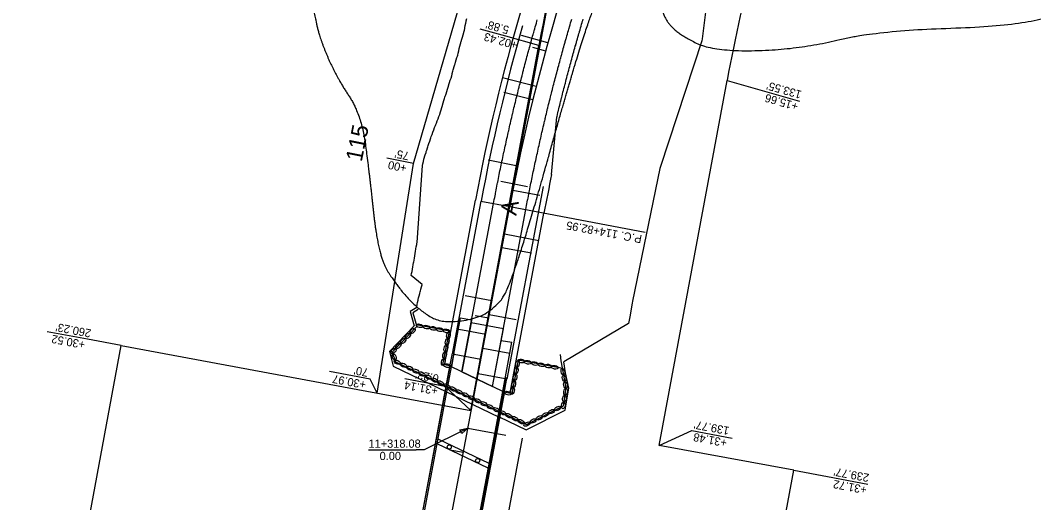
# Model space of a CAD drawing. Extents: x 674098 to 689971, y 764717 to 781049.
# Drawn here: x 688378 to 689119, y 766344 to 766697 of the extents above; entities that cross this region are included whole.
import ezdxf

# ---------------------------------------------------------------- set-up
doc = ezdxf.new("R2010")
doc.units = 0
for name, color, linetype in [('BRIDGE', 7, 'Continuous'), ('FLOODPLAIN', 7, 'Continuous'), ('Level 1', 7, 'Continuous'), ('R_Approach Slab', 7, 'Continuous'), ('R_GUARDRAIL S1', 7, 'Continuous'), ('R_GUARDRAIL S2', 7, 'Continuous'), ('R_Horz Alg', 7, 'Continuous'), ('R_Horz Alg Station', 7, 'Continuous'), ('R_Horz Alg Station Annot', 7, 'Continuous'), ('R_No Plot', 7, 'Continuous'), ('R_Proposed Const Limits', 7, 'Continuous'), ('R_Proposed Const Limits Stage 2', 7, 'Continuous'), ('R_Proposed Riprap', 7, 'Continuous'), ('R_Proposed Riprap MOT Stage 2', 7, 'Continuous'), ('R_Proposed Road', 7, 'Continuous'), ('R_Proposed Shoulder S1', 7, 'Continuous'), ('R_ROW', 7, 'Continuous'), ('R_ROW Annot', 7, 'Continuous'), ('S_EXIST_ROW', 7, 'Continuous'), ('S_EXIST_ROW Annot', 7, 'Continuous')]:
    doc.layers.add(name, color=color, linetype=linetype)

msp = doc.modelspace()

# ---------------------------------------------------------------- linework, layer by layer
at = {"layer": 'BRIDGE'}
for p, q in [((688645.49, 766197.09), (688691.88, 766443.79)), ((688645.65, 766197.06), (688692.05, 766443.76)), ((688646.72, 766196.86), (688693.11, 766443.56)), ((688693.11, 766443.56), (688691.88, 766443.79)), ((688730.44, 766425.64), (688693.11, 766443.56)), ((688684.05, 766178.93), (688730.44, 766425.64)), ((688685.11, 766178.73), (688731.51, 766425.44)), ((688731.67, 766425.41), (688685.28, 766178.7)), ((688730.44, 766425.64), (688731.67, 766425.41))]:
    msp.add_line(p, q, dxfattribs=at)
for points in [[(688691.88, 766443.79), (688693.73, 766453.62), (688694.71, 766453.44), (688694.25, 766450.98), (688693.11, 766443.56)], [(688731.67, 766425.41), (688733.52, 766435.23), (688732.54, 766435.42), (688732.07, 766432.96), (688730.44, 766425.64)]]:
    msp.add_lwpolyline(points, dxfattribs=at)
at = {"layer": 'FLOODPLAIN'}
for points in [[(688557.23, 766766.05), (688591.58, 766711.04), (688595.35, 766687.04), (688608.48, 766656.15), (688627.02, 766628.3), (688632.82, 766586.19), (688639.4, 766524.53), (688653.57, 766501.98), (688669.3, 766485), (688687.59, 766474.45), (688723.13, 766481.9), (688739.6, 766509.51), (688789, 766687.63), (688806.98, 766729.19), (688822.47, 766746.61), (688835.88, 766751.3), (688842.63, 766741.88), (688846.4, 766712.12), (688847.97, 766698.77), (688859.62, 766686.41), (688884.96, 766674.2), (688946.59, 766675.74), (689003.92, 766689.73), (689113.2, 766693.11), (689155.64, 766709.56), (689222.69, 766748.31), (689278.94, 766804.47), (689325.37, 766856.38), (689397.34, 766962.93), (689435.45, 766991.81), (689488.41, 767032.29), (689550.62, 767060.41), (689676.67, 767118.63), (689783.6, 767157.05), (689856.65, 767174.65), (689971.45, 767193.2)], [(687636.99, 766648.35), (687660.7, 766676.39), (687679.12, 766678.93), (687695.79, 766668.17), (687704.23, 766666.19), (687721.96, 766671.63), (687744.74, 766707.43), (687761.28, 766716.58), (687819.2, 766729.75), (687857.32, 766757.84), (687886.19, 766778.49), (687909.82, 766800.04), (687916.33, 766827.84), (687921.35, 766849.28), (687933.23, 766850.3), (687942.45, 766841.87), (687953.68, 766811.48), (687955.55, 766791.78), (687937.94, 766767.25), (687928.38, 766752.25), (687934.01, 766743.77), (687949.02, 766743.84), (687978.06, 766759.86), (688017.53, 766789.79), (688029.63, 766786.96), (688058.51, 766774.59), (688076.54, 766770.37), (688098.38, 766788.35), (688128.58, 766823.59), (688146.89, 766829.88), (688224.87, 766848.43), (688351.93, 766870.25), (688387.57, 766861.9), (688478.61, 766846.38), (688494.31, 766842.7), (688540.43, 766797.53), (688557.23, 766766.05)]]:
    msp.add_open_spline(points, degree=2, dxfattribs=at)
at = {"layer": 'Level 1'}
for p, q in [((688719.86, 766369.36), (688682.53, 766387.29)), ((688720.51, 766372.8), (688683.18, 766390.73))]:
    msp.add_line(p, q, dxfattribs=at)
for centre in [(688691.35, 766384.93), (688712.13, 766374.95)]:
    msp.add_circle(centre, 1.5, dxfattribs=at)
at = {"layer": 'R_Approach Slab'}
for p, q in [((688693.11, 766443.56), (688699.65, 766479.47)), ((688699.65, 766479.47), (688707.73, 766478)), ((688707.73, 766478), (688707.31, 766475.77)), ((688729.32, 766462.94), (688736.98, 766461.55)), ((688730.44, 766425.64), (688736.98, 766461.55))]:
    msp.add_line(p, q, dxfattribs=at)
msp.add_lwpolyline([(688700.58, 766439.98), (688722.98, 766429.22), (688730.92, 766471.47), (688707.31, 766475.77)], close=True, dxfattribs=at)
at = {"layer": 'R_GUARDRAIL S1'}
msp.add_line((688693.62, 766453.03), (688714.63, 766564.76), dxfattribs=at)
msp.add_lwpolyline([(688719.48, 766367.32), (688719.46, 766367.25)], dxfattribs=at)
msp.add_arc((690143.23, 766296.11), 1453.64, 164.14725, 169.35, dxfattribs=at)
at = {"layer": 'R_GUARDRAIL S2'}
msp.add_line((688760.05, 766575.61), (688733.41, 766434.64), dxfattribs=at)
at = {"layer": 'R_Horz Alg'}
for p, q in [((688735.51, 766560.83), (688775.27, 766772.26)), ((688649.13, 766101.47), (688735.51, 766560.83)), ((688649.13, 766101.47), (688735.51, 766560.83))]:
    msp.add_line(p, q, dxfattribs=at)
msp.add_arc((690143.23, 766296.11), 1432.39, 152.26653, 169.35, dxfattribs=at)
msp.add_arc((690143.23, 766296.11), 1432.39, 152.26653, 169.35, dxfattribs=at)
at = {"layer": 'R_Horz Alg Station'}
for points in [[(688752.17, 766677.49), (688761.82, 766674.85)], [(688728.96, 766579.53), (688748.57, 766575.6)], [(688735.51, 766560.83), (688834.5, 766542.22)], [(688710.36, 766481.15), (688720.18, 766479.31)], [(688691.88, 766382.88), (688701.7, 766381.03)]]:
    msp.add_lwpolyline(points, dxfattribs=at)
at = {"layer": 'R_No Plot'}
for p, q in [((688763.42, 766680.65), (688744.16, 766686.02)), ((688754.93, 766648.76), (688730.22, 766655.04)), ((688752.5, 766639.06), (688731.14, 766644.33)), ((688741.38, 766590.32), (688719.85, 766594.84)), ((688737.82, 766572.96), (688757.48, 766569.15)), ((688714.41, 766564.8), (688735.51, 766560.83)), ((688756.76, 766535.82), (688731.7, 766540.53)), ((688751.47, 766526.64), (688729.85, 766530.71)), ((688702.93, 766495.8), (688722.59, 766492.1)), ((688740.26, 766477.87), (688720.61, 766481.57)), ((688698.31, 766471.23), (688717.97, 766467.53)), ((688694.85, 766452.8), (688714.5, 766449.11)), ((688735.64, 766453.3), (688715.99, 766457)), ((688732.18, 766434.88), (688712.52, 766438.57)), ((688705.04, 766398.8), (688732.61, 766393.61)), ((688744.63, 766391.33), (688710.59, 766209.69)), ((688632.33, 766382.88), (688667.13, 766382.88))]:
    msp.add_line(p, q, dxfattribs=at)
msp.add_lwpolyline([(688705.04, 766398.8), (688673.13, 766382.88), (688667.13, 766382.88)], dxfattribs=at)
msp.add_lwpolyline([(688705.04, 766398.8), (688700.48, 766394.9), (688699.19, 766397.5)], close=True, dxfattribs=at)
at = {"layer": 'R_Proposed Const Limits'}
for points in [[(688667.68, 766487.44), (688667.95, 766489.07), (688667.96, 766489.13), (688668.23, 766490.71), (688668.51, 766492.34), (688668.63, 766492.77), (688668.93, 766493.95), (688669.35, 766495.55), (688669.77, 766497.16), (688670.19, 766498.77), (688670.22, 766498.88), (688670.61, 766500.38), (688671.03, 766501.99), (688671.45, 766503.59), (688671.48, 766503.73), (688663.59, 766510.3), (688663.84, 766511.77), (688664.14, 766513.4), (688664.43, 766515.03), (688664.72, 766516.66), (688664.73, 766516.69), (688665.01, 766518.3), (688665.3, 766519.93), (688665.34, 766520.15), (688665.59, 766521.56), (688665.87, 766523.19), (688666.15, 766524.83), (688666.42, 766526.46), (688666.7, 766528.1), (688666.99, 766529.73), (688667.03, 766530), (688667.27, 766531.36), (688667.54, 766533), (688667.73, 766534.12), (688667.82, 766534.63), (688671.83, 766590.98), (688672.06, 766592.05), (688672.41, 766593.75), (688672.78, 766595.45), (688673.25, 766596.92), (688673.31, 766597.12), (688673.83, 766598.78), (688674.36, 766600.44), (688674.58, 766601.11), (688674.9, 766602.1), (688675.45, 766603.76), (688675.71, 766604.57), (688675.99, 766605.42), (688676.54, 766607.08), (688677.09, 766608.74), (688677.64, 766610.39), (688677.88, 766611.11), (688678.19, 766612.05), (688678.24, 766612.19), (688678.8, 766613.69), (688679.42, 766615.33), (688680.05, 766616.97), (688680.68, 766618.6), (688681.11, 766619.73), (688681.3, 766620.24), (688681.6, 766621), (688681.93, 766621.87), (688682.56, 766623.51), (688683.19, 766625.14), (688683.82, 766626.77), (688684.01, 766627.25), (688684.36, 766628.1), (688684.45, 766628.41), (688684.95, 766630.07), (688685.2, 766630.9), (688685.45, 766631.73), (688685.94, 766633.39), (688686.39, 766634.87), (688686.44, 766635.05), (688686.95, 766636.71), (688687.45, 766638.37), (688687.96, 766640.03), (688688.22, 766640.92), (688688.46, 766641.69), (688688.73, 766642.5), (688689, 766643.34), (688689.53, 766644.99), (688690.05, 766646.65), (688690.56, 766648.3), (688691.08, 766649.96), (688691.13, 766650.11), (688691.37, 766650.89), (688691.59, 766651.61), (688692.11, 766653.26), (688692.63, 766654.92), (688693.16, 766656.57), (688693.45, 766657.74), (688693.56, 766658.25), (688693.95, 766659.93), (688694.19, 766660.94), (688694.39, 766661.61), (688694.9, 766663.26), (688695.42, 766664.91), (688695.57, 766665.4), (688695.94, 766666.56), (688696.46, 766668.22), (688696.98, 766669.87), (688697.31, 766670.91), (688697.5, 766671.52), (688697.84, 766673.03), (688697.88, 766673.2), (688698.26, 766674.89), (688698.64, 766676.58), (688699.05, 766678.26), (688699.53, 766679.92), (688699.77, 766680.75), (688699.86, 766681.03), (688700.02, 766681.58), (688700.5, 766683.24), (688700.99, 766684.9), (688701.47, 766686.56), (688701.96, 766688.21), (688702.01, 766688.38), (688702.38, 766689.89), (688702.62, 766691.08), (688702.72, 766691.59), (688703.06, 766693.29), (688703.41, 766694.99), (688703.65, 766696.18), (688703.76, 766696.69), (688704.11, 766698.38)], [(688667.7, 766486.99), (688662.77, 766483.95), (688665.7, 766473.66), (688647.65, 766454.81), (688650.4, 766444.04), (688727.81, 766406.86)]]:
    msp.add_lwpolyline(points, dxfattribs=at)
at = {"layer": 'R_Proposed Const Limits Stage 2'}
for points in [[(688881.93, 766728.74), (688876.21, 766683.7), (688875.85, 766682.21), (688845.71, 766590.1), (688845.35, 766588.6), (688825.36, 766491.52), (688825.08, 766490.11), (688823.32, 766480.26), (688822.44, 766475.34), (688775.03, 766447.35)], [(688727.77, 766406.88), (688747.5, 766397.41), (688775.99, 766411.91), (688778.64, 766427.93), (688776.43, 766439.21), (688775.03, 766447.35)]]:
    msp.add_lwpolyline(points, dxfattribs=at)
at = {"layer": 'R_Proposed Riprap'}
msp.add_lwpolyline([(688668.6, 766485.52), (688664.78, 766483.17), (688667.62, 766473.18), (688649.63, 766454.39), (688652.16, 766447.32), (688747.86, 766401.36), (688774.82, 766415.08), (688776.9, 766427.9), (688774.74, 766438.9), (688773.16, 766448.04), (688772.62, 766452.51)], dxfattribs=at)
for centre, major_axis in [((688669.66, 766473.59), (2.46, -0.47)), ((688674.6, 766472.65), (2.46, -0.47)), ((688679.53, 766471.72), (2.46, -0.47)), ((688661.08, 766466.13), (1.73, 1.81)), ((688664.55, 766469.76), (1.73, 1.81)), ((688684.46, 766470.78), (2.46, -0.47)), ((688689.39, 766469.84), (2.46, -0.47)), ((688690.78, 766466.77), (-0.48, -2.45)), ((688654.14, 766458.88), (1.73, 1.81)), ((688657.61, 766462.51), (1.73, 1.81)), ((688688.86, 766456.92), (-0.48, -2.45)), ((688689.82, 766461.84), (-0.48, -2.45)), ((688650.67, 766455.26), (1.73, 1.81)), ((688651.01, 766450.98), (-0.84, 2.36)), ((688687.89, 766451.99), (-0.48, -2.45)), ((688653.3, 766446.94), (-2.25, 1.08)), ((688657.82, 766444.76), (-2.25, 1.08)), ((688662.35, 766442.59), (-2.25, 1.08)), ((688686.93, 766447.06), (-0.48, -2.45)), ((688689.79, 766444.47), (2.46, -0.46)), ((688666.87, 766440.42), (-2.25, 1.08)), ((688671.4, 766438.25), (-2.25, 1.08)), ((688675.92, 766436.07), (-2.25, 1.08)), ((688680.45, 766433.9), (-2.25, 1.08)), ((688684.97, 766431.73), (-2.25, 1.08)), ((688689.5, 766429.55), (-2.25, 1.08)), ((688694.02, 766427.38), (-2.25, 1.08)), ((688698.55, 766425.21), (-2.25, 1.08)), ((688703.07, 766423.03), (-2.25, 1.08)), ((688707.6, 766420.86), (-2.25, 1.08)), ((688712.12, 766418.69), (-2.25, 1.08)), ((688716.65, 766416.52), (-2.25, 1.08)), ((688721.17, 766414.34), (-2.25, 1.08)), ((688725.7, 766412.17), (-2.25, 1.08))]:
    msp.add_ellipse(centre, major_axis=major_axis, ratio=0.517889, dxfattribs=at)
at = {"layer": 'R_Proposed Riprap MOT Stage 2'}
for points in [[(688691.63, 766444.28), (688686.72, 766445.2), (688691.49, 766469.6), (688667.23, 766474.21)], [(688773.04, 766442.55), (688741.62, 766448.4), (688737.06, 766423.86), (688731.83, 766424.97)]]:
    msp.add_lwpolyline(points, dxfattribs=at)
for centre, major_axis in [((688740.36, 766440.79), (0.46, 2.46)), ((688741.28, 766445.72), (0.46, 2.46)), ((688743.88, 766447.83), (2.46, -0.46)), ((688748.82, 766446.91), (2.46, -0.46)), ((688753.75, 766445.99), (2.46, -0.46)), ((688758.69, 766445.07), (2.46, -0.46)), ((688763.62, 766444.15), (2.46, -0.46)), ((688768.56, 766443.23), (2.46, -0.46)), ((688739.44, 766435.85), (0.46, 2.46)), ((688774.38, 766440.08), (0.43, -2.46)), ((688775.32, 766435.15), (0.48, -2.45)), ((688737.61, 766425.98), (0.46, 2.46)), ((688738.52, 766430.92), (0.46, 2.46)), ((688776.29, 766430.22), (0.48, -2.45)), ((688734.26, 766424.3), (2.45, -0.52)), ((688775.52, 766420.38), (-0.4, -2.47)), ((688776.33, 766425.33), (-0.4, -2.47)), ((688770.56, 766413.08), (-2.23, -1.13)), ((688774.72, 766415.42), (-0.4, -2.47)), ((688730.23, 766410), (-2.25, 1.08)), ((688734.75, 766407.82), (-2.25, 1.08)), ((688739.28, 766405.65), (-2.25, 1.08)), ((688757.14, 766406.25), (-2.23, -1.13)), ((688761.61, 766408.53), (-2.23, -1.13)), ((688766.09, 766410.81), (-2.23, -1.13)), ((688743.8, 766403.48), (-2.25, 1.08)), ((688748.19, 766401.7), (-2.23, -1.13)), ((688752.66, 766403.98), (-2.23, -1.13))]:
    msp.add_ellipse(centre, major_axis=major_axis, ratio=0.517889, dxfattribs=at)
at = {"layer": 'R_Proposed Road'}
for points in [[(688700.58, 766439.98), (688723.72, 766563.05), (688723.75, 766563.22), (688724.02, 766564.62), (688724.28, 766566.02), (688724.55, 766567.42), (688724.82, 766568.82), (688725.05, 766570.03), (688725.09, 766570.23), (688725.16, 766570.6), (688725.36, 766571.63), (688725.63, 766573.03), (688725.91, 766574.43), (688726.18, 766575.83), (688726.46, 766577.23), (688726.64, 766578.15), (688726.74, 766578.63), (688727, 766579.92), (688727.02, 766580.03), (688727.3, 766581.42), (688727.58, 766582.82), (688727.87, 766584.22), (688728.15, 766585.62), (688728.17, 766585.69), (688728.44, 766587.02), (688728.73, 766588.42), (688729.01, 766589.8), (688729.02, 766589.81), (688729.31, 766591.21), (688729.6, 766592.61), (688729.73, 766593.22), (688729.89, 766594), (688730.19, 766595.4), (688730.48, 766596.79), (688730.78, 766598.19), (688731.08, 766599.58), (688731.1, 766599.67), (688731.33, 766600.74), (688731.38, 766600.98), (688731.68, 766602.37), (688731.99, 766603.77), (688732.29, 766605.16), (688732.6, 766606.56), (688732.9, 766607.95), (688732.97, 766608.25), (688733.21, 766609.34), (688733.25, 766609.52), (688733.52, 766610.74), (688733.84, 766612.13), (688734.15, 766613.52), (688734.46, 766614.91), (688734.65, 766615.76), (688734.78, 766616.31), (688735.09, 766617.7), (688735.41, 766619.09), (688735.45, 766619.26), (688735.48, 766619.36), (688735.73, 766620.48), (688736.05, 766621.87), (688736.37, 766623.25), (688736.38, 766623.26), (688736.7, 766624.65), (688737.03, 766626.04), (688737.35, 766627.43), (688737.68, 766628.81), (688737.77, 766629.18), (688738.01, 766630.2), (688738.14, 766630.74), (688738.34, 766631.59), (688738.67, 766632.98), (688739.01, 766634.37), (688739.34, 766635.75), (688739.68, 766637.14), (688739.94, 766638.21), (688740.01, 766638.53), (688740.13, 766638.98), (688740.35, 766639.91), (688740.69, 766641.3), (688741.04, 766642.68), (688741.38, 766644.07), (688741.72, 766645.45), (688741.78, 766645.68), (688742.07, 766646.84), (688742.42, 766648.22), (688742.55, 766648.77), (688742.76, 766649.61), (688743.11, 766650.99), (688743.47, 766652.37), (688743.66, 766653.14), (688743.82, 766653.76), (688744.17, 766655.14), (688744.53, 766656.52), (688744.88, 766657.9), (688745.05, 766658.54), (688745.24, 766659.28), (688745.58, 766660.58), (688745.6, 766660.66), (688745.96, 766662.04), (688746.33, 766663.42), (688746.69, 766664.8), (688747.05, 766666.18), (688747.42, 766667.56), (688747.54, 766668.02), (688747.61, 766668.29), (688747.79, 766668.94), (688748.16, 766670.32), (688748.53, 766671.7), (688748.9, 766673.08), (688749.27, 766674.45), (688749.54, 766675.44), (688749.65, 766675.83), (688750.02, 766677.21), (688750.25, 766678.02), (688750.4, 766678.58), (688750.78, 766679.96), (688751.16, 766681.33), (688751.54, 766682.71), (688751.58, 766682.86), (688751.92, 766684.08), (688752.31, 766685.46), (688752.69, 766686.83), (688752.95, 766687.74), (688753.08, 766688.21), (688753.47, 766689.58), (688753.66, 766690.26), (688753.86, 766690.95), (688754.25, 766692.32), (688754.64, 766693.7), (688755.03, 766695.07), (688755.43, 766696.44), (688755.71, 766697.43)], [(688722.98, 766429.22), (688747.31, 766558.61), (688747.34, 766558.78), (688747.6, 766560.16), (688747.86, 766561.54), (688748.12, 766562.91), (688748.39, 766564.29), (688748.62, 766565.48), (688748.65, 766565.67), (688748.72, 766566.04), (688748.92, 766567.05), (688749.19, 766568.43), (688749.46, 766569.8), (688749.73, 766571.18), (688750, 766572.56), (688750.18, 766573.46), (688750.28, 766573.93), (688750.53, 766575.21), (688750.55, 766575.31), (688750.83, 766576.68), (688751.1, 766578.06), (688751.38, 766579.43), (688751.66, 766580.81), (688751.68, 766580.87), (688751.95, 766582.18), (688752.23, 766583.56), (688752.51, 766584.92), (688752.51, 766584.93), (688752.8, 766586.31), (688753.09, 766587.68), (688753.21, 766588.28), (688753.38, 766589.05), (688753.67, 766590.43), (688753.96, 766591.8), (688754.25, 766593.17), (688754.55, 766594.54), (688754.56, 766594.62), (688754.79, 766595.68), (688754.84, 766595.91), (688755.14, 766597.29), (688755.44, 766598.66), (688755.74, 766600.03), (688756.04, 766601.4), (688756.34, 766602.77), (688756.4, 766603.06), (688756.64, 766604.14), (688756.68, 766604.31), (688756.95, 766605.51), (688757.25, 766606.88), (688757.56, 766608.25), (688757.87, 766609.62), (688758.06, 766610.44), (688758.18, 766610.98), (688758.49, 766612.35), (688758.81, 766613.72), (688758.84, 766613.89), (688758.87, 766613.98), (688759.12, 766615.09), (688759.44, 766616.46), (688759.75, 766617.82), (688759.75, 766617.82), (688760.07, 766619.19), (688760.39, 766620.56), (688760.71, 766621.92), (688761.04, 766623.29), (688761.12, 766623.64), (688761.36, 766624.65), (688761.48, 766625.18), (688761.68, 766626.02), (688762.01, 766627.38), (688762.34, 766628.75), (688762.67, 766630.11), (688763, 766631.47), (688763.26, 766632.53), (688763.33, 766632.84), (688763.44, 766633.28), (688763.66, 766634.2), (688764, 766635.56), (688764.33, 766636.93), (688764.67, 766638.29), (688765.01, 766639.65), (688765.07, 766639.87), (688765.35, 766641.01), (688765.69, 766642.37), (688765.83, 766642.91), (688766.03, 766643.73), (688766.38, 766645.09), (688766.72, 766646.45), (688766.92, 766647.2), (688767.07, 766647.81), (688767.42, 766649.17), (688767.77, 766650.53), (688768.12, 766651.89), (688768.28, 766652.51), (688768.47, 766653.25), (688768.8, 766654.53), (688768.83, 766654.61), (688769.18, 766655.96), (688769.54, 766657.32), (688769.89, 766658.68), (688770.25, 766660.03), (688770.61, 766661.39), (688770.73, 766661.84), (688770.8, 766662.1), (688770.97, 766662.75), (688771.34, 766664.1), (688771.7, 766665.46), (688772.07, 766666.81), (688772.43, 766668.17), (688772.7, 766669.14), (688772.8, 766669.52), (688773.17, 766670.87), (688773.39, 766671.68), (688773.54, 766672.23), (688773.92, 766673.58), (688774.29, 766674.93), (688774.66, 766676.29), (688774.7, 766676.43), (688775.04, 766677.64), (688775.42, 766678.99), (688775.8, 766680.34), (688776.05, 766681.23), (688776.18, 766681.69), (688776.56, 766683.04), (688776.75, 766683.72), (688776.94, 766684.39), (688777.33, 766685.74), (688777.71, 766687.09), (688778.1, 766688.44), (688778.49, 766689.79), (688778.77, 766690.77), (688778.83, 766690.99), (688778.88, 766691.13), (688779.27, 766692.48), (688779.66, 766693.83), (688780.05, 766695.18), (688780.45, 766696.52), (688780.84, 766697.87)]]:
    msp.add_lwpolyline(points, dxfattribs=at)
at = {"layer": 'R_Proposed Shoulder S1'}
for p, q in [((688766.19, 766584.39), (688770.03, 766626.53)), ((688687.77, 766444.91), (688710.45, 766565.54)), ((688735.85, 766424.62), (688760.57, 766556.12))]:
    msp.add_line(p, q, dxfattribs=at)
for points in [[(688781.7, 766671.73), (688782, 766672.8), (688782.37, 766674.14), (688782.41, 766674.29), (688782.74, 766675.49), (688783.12, 766676.83), (688783.5, 766678.18), (688783.75, 766679.06), (688783.87, 766679.52), (688784.25, 766680.86), (688784.44, 766681.53), (688784.63, 766682.2), (688785.02, 766683.55), (688785.4, 766684.89), (688785.78, 766686.23), (688786.17, 766687.57), (688786.45, 766688.54), (688786.51, 766688.76), (688786.56, 766688.91), (688786.95, 766690.25), (688787.34, 766691.59), (688787.73, 766692.93), (688788.12, 766694.27), (688788.52, 766695.61), (688788.62, 766695.98), (688788.91, 766696.94), (688789.22, 766698.01)], [(688770.03, 766626.53), (688770.11, 766626.87), (688770.44, 766628.23), (688770.77, 766629.59), (688771.03, 766630.63), (688771.1, 766630.94), (688771.21, 766631.38), (688771.43, 766632.3), (688771.76, 766633.65), (688772.1, 766635.01), (688772.43, 766636.36), (688772.77, 766637.71), (688772.83, 766637.93), (688773.11, 766639.07), (688773.45, 766640.42), (688773.58, 766640.95), (688773.79, 766641.77), (688774.13, 766643.13), (688774.48, 766644.48), (688774.67, 766645.23), (688774.82, 766645.83), (688775.17, 766647.18), (688775.51, 766648.53), (688775.86, 766649.89), (688776.02, 766650.51), (688776.21, 766651.24), (688776.54, 766652.51), (688776.56, 766652.59), (688776.92, 766653.94), (688777.27, 766655.29), (688777.63, 766656.64), (688777.98, 766657.98), (688778.34, 766659.33), (688778.46, 766659.78), (688778.53, 766660.04), (688778.7, 766660.68), (688779.06, 766662.03), (688779.42, 766663.38), (688779.79, 766664.72), (688780.15, 766666.07), (688780.42, 766667.04), (688780.52, 766667.42), (688780.89, 766668.76), (688781.24, 766670.07), (688781.7, 766671.73)]]:
    msp.add_lwpolyline(points, dxfattribs=at)
for radius, start in [(1457.89, 163.74725), (1406.89, 168.17607)]:
    msp.add_arc((690143.23, 766296.11), radius, start, 169.35, dxfattribs=at)
at = {"layer": 'R_ROW'}
msp.add_line((688638.63, 766424.41), (688665.23, 766592.3), dxfattribs=at)
msp.add_lwpolyline([(688665.23, 766592.3), (688709.06, 766743.68), (688790.56, 766926.6)], dxfattribs=at)
at = {"layer": 'R_ROW Annot'}
for points in [[(688665.23, 766592.3), (688645.62, 766596.23)], [(688638.63, 766424.41), (688633.61, 766434.49), (688603.88, 766440.08)]]:
    msp.add_lwpolyline(points, dxfattribs=at)
at = {"layer": 'S_EXIST_ROW'}
for p, q in [((688707.23, 766411.68), (688756.79, 766678.76)), ((688844.88, 766386.13), (688894.44, 766653.21)), ((688405.98, 766213.31), (688451.6, 766459.11)), ((688451.6, 766459.11), (688707.23, 766411.68)), ((688943.2, 766367.89), (688844.88, 766386.13)), ((688897.59, 766122.08), (688943.2, 766367.89))]:
    msp.add_line(p, q, dxfattribs=at)
for radius, start in [(1472.39, 159.28665), (1332.39, 165.34172)]:
    msp.add_arc((690204.47, 766410.11), radius, start, 169.48718, dxfattribs=at)
at = {"layer": 'S_EXIST_ROW Annot'}
for points in [[(688756.79, 766678.76), (688732.69, 766685.41), (688713.86, 766690.61)], [(688894.44, 766653.21), (688918.48, 766646.34), (688947.32, 766638.09)], [(688451.6, 766459.11), (688427.03, 766463.74), (688397.54, 766469.28)], [(688707.23, 766411.68), (688688.46, 766429.3), (688658.98, 766434.85)], [(688844.88, 766386.13), (688868.55, 766396.98), (688898.04, 766391.43)], [(688943.2, 766367.89), (688967.77, 766363.27), (688997.25, 766357.72)]]:
    msp.add_lwpolyline(points, dxfattribs=at)

# ---------------------------------------------------------------- texts
at = {"layer": 'R_Horz Alg'}
msp.add_text('A', height=12, rotation=79.35, dxfattribs=at).set_placement((688740.3, 766553.82))
at = {"layer": 'R_Horz Alg Station Annot'}
for s, height, rotation, p in [('115', 12, 78.66807, (688627.36, 766593.15)), ('P.C. 114+82.95', 6, 169.35, (688832.58, 766539.82))]:
    msp.add_text(s, height=height, rotation=rotation, dxfattribs=at).set_placement(p)
at = {"layer": 'R_No Plot'}
for s, p in [('11+318.08', (688632.33, 766384.38)), ('0.00', (688640.44, 766375.38))]:
    msp.add_text(s, height=6, dxfattribs=at).set_placement(p)
at = {"layer": 'R_ROW Annot'}
for s, rotation, p in [("75'", 168.66807, (688662.42, 766600.53)), ('+00', 168.66807, (688660.65, 766591.7)), ("70'", 169.35, (688632.57, 766442.07)), ('+30.97', 169.35, (688630.91, 766433.22))]:
    msp.add_text(s, height=6, rotation=rotation, dxfattribs=at).set_placement(p)
at = {"layer": 'S_EXIST_ROW Annot'}
for s, rotation, p in [("5.88'", 164.57091, (688735.56, 766692.62)), ('+02.43', 164.57091, (688741.65, 766681.6)), ("133.55'", 164.04164, (688949.39, 766645.3)), ('+15.66', 164.04164, (688946.91, 766636.65)), ("260.23'", 169.35, (688429.95, 766470.82)), ('+30.52', 169.35, (688425.6, 766462.48)), ("0.23'", 169.35, (688684.09, 766437.73)), ('+31.14', 169.35, (688683.45, 766428.69)), ("139.77'", 169.35, (688896.44, 766399.49)), ('+31.48', 169.35, (688894.77, 766390.64)), ("239.77'", 169.35, (688998.64, 766365.09)), ('+31.72', 169.35, (688996.98, 766356.25))]:
    msp.add_text(s, height=6, rotation=rotation, dxfattribs=at).set_placement(p)

doc.saveas('drawing.dxf')
